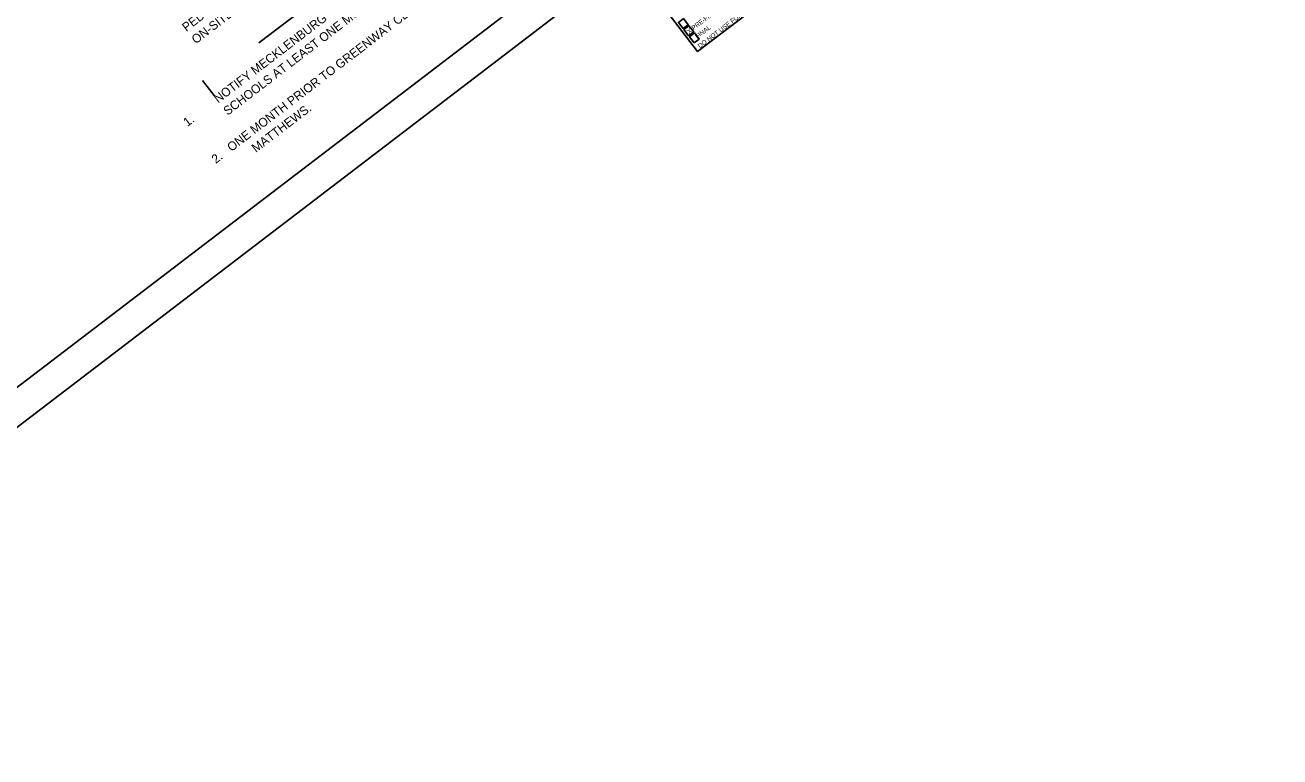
# Model space of a CAD drawing. Extents: x -606 to 2396, y -305 to 3662.
# Drawn here: x 1012 to 2005, y 50 to 630 of the extents above; entities that cross this region are included whole.
import ezdxf

# ---------------------------------------------------------------- set-up
doc = ezdxf.new("R2010")
doc.units = 0
for name, color, linetype in [('DEV BORDER CELL', 7, 'Continuous'), ('DEV SUBMITTAL STAMP CELL', 7, 'Continuous'), ('Gray Area Fill Shapes', 7, 'Continuous'), ('Scratch_Level_4', 7, 'Continuous'), ('Sheet Plot Border Outside CELL', 7, 'Continuous'), ('TCP Linework', 7, 'Continuous'), ('Text', 7, 'Continuous')]:
    doc.layers.add(name, color=color, linetype=linetype)

msp = doc.modelspace()

# ---------------------------------------------------------------- linework, layer by layer
at = {"layer": 'DEV BORDER CELL'}
for p, q in [((786.1, 175.54), (1961.32, 1074.19)), ((1196.56, 615.86), (1417.36, 784.69))]:
    msp.add_line(p, q, dxfattribs=at)
at = {"layer": 'DEV SUBMITTAL STAMP CELL'}
msp.add_lwpolyline([(1512.5, 649.81), (1585.56, 705.68), (1616.75, 664.9), (1543.68, 609.03)], close=True, dxfattribs=at)
at = {"layer": 'Gray Area Fill Shapes'}
msp.add_lwpolyline([(1512.5, 649.81), (1585.56, 705.68), (1616.75, 664.9), (1543.68, 609.03)], close=True, dxfattribs=at)
at = {"layer": 'Scratch_Level_4'}
msp.add_line((1152.1, 586.22), (1161.22, 574.31), dxfattribs=at)
at = {"layer": 'Sheet Plot Border Outside CELL'}
msp.add_lwpolyline([(663.64, 50.42), (2004.54, 1075.77), (1336.37, 1949.58), (-4.54, 924.23)], close=True, dxfattribs=at)
at = {"layer": 'TCP Linework'}
for points in [[(1532.33, 627.25), (1536.29, 630.28), (1532.5, 635.23), (1528.54, 632.2)], [(1536.68, 621.56), (1540.64, 624.59), (1536.86, 629.54), (1532.9, 626.51)], [(1541.03, 615.87), (1544.99, 618.9), (1541.21, 623.85), (1537.25, 620.82)]]:
    msp.add_lwpolyline(points, close=True, dxfattribs=at)

# ---------------------------------------------------------------- texts
at = {"layer": 'DEV SUBMITTAL STAMP CELL'}
for s, p in [('DO NOT USE FOR CONSTRUCTION', (1545.62, 611.5)), ('X PRE-FINAL', (1536.88, 622.94)), ('  FINAL', (1541.25, 617.22))]:
    msp.add_text(s, height=3.6, rotation=37.40396, dxfattribs=at).set_placement(p)
at = {"layer": 'Text'}
for s, p in [(' NOTIFY MECKLENBURG COUNTY EMERGENCY SERVICES AND PUBLIC', (1162.28, 566.31)), ('2.   ONE MONTH PRIOR TO GREENWAY CLOSURE, NOTIFY THE TOWN OF', (1162.45, 519.99)), (' SCHOOLS AT LEAST ONE MONTH PRIOR TO ROAD CLOSURE.', (1169.75, 556.54)), ('     PEDESTRIAN ACCOMMODATIONS', (1128.87, 616.61)), ('     ON-SITE DETOURS', (1136.34, 606.84)), ('1.', (1140.04, 549.3)), (' MATTHEWS.', (1192.16, 527.23))]:
    msp.add_text(s, height=7, rotation=37.40396, dxfattribs=at).set_placement(p)

doc.saveas('drawing.dxf')
